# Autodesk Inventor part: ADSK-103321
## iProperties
Created: 2000-08
Part Number: ADSK-103321
Description: Helical Spring Lock Washer
Document SubType Name: Modeling
Standard: ASME B18.21.1 - 3/8  Regular. Carbon Steel
Density: 1 g/cm^3
Control State: 0
Master: False
Checked Out: False
Shininess: 0.0
Density: 0.0
Volumn: 0.0
Area: 0.0
PropertySet Name: Model Information
Author: Administrator
